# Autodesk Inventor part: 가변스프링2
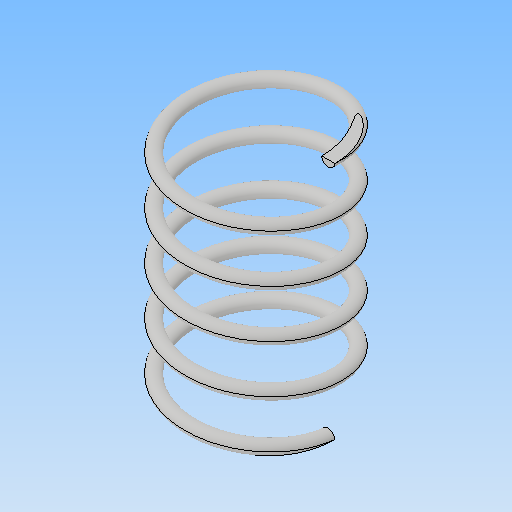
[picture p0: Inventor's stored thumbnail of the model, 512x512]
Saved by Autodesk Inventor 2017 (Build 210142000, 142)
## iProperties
Part Number: 가변스프링2
Material: 일반
Document SubType Name: Modeling
Designer: MRC
Density: 1 g/cm^3
Appearance: 기본값
Mass: 1.07362 g
Surface Area: 21.7305 cm^2
Volume: 1.07362 cm^3
Author: MRC
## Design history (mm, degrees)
sketch "스케치1"
  geometry: L1 (0, 0)-(0, 36.411); L2 (0, 0)-(11, 0); L3 (0, 36.411)-(11, 36.411); C1 r 1 at (11, 0)
  constraints: 6 end point, 2 horizontal, 1 centre point, 1 coincident, 1 vertical
  dimensions: "d0" = 36.4112 distance of L1.start L1.end (derived); "d1" = 11 distance of L1.start L2.end; "d2" = 2 diameter of C1
feature "코일1" pitch "d3" = 10; turns "d5" = 5; dims "d4" = 36.4112 (= d0), "d6" = 0, angle "d7" = 90 deg, angle "d8" = 90 deg, "d9" = 0, "d10" = 0
sketch "스케치2"
  geometry: L1 (36.411, 15)-(0, 15); L2 (0, 15)-(0, -15); L3 (0, -15)-(36.411, -15); L4 (36.411, -15)-(36.411, 15); 2 further points
  constraints: 8 end point, 2 parallel, 1 coincident, 1 horizontal, 1 midpoint, 1 perpendicular
  dimensions: "d11" = 30 distance of L3.end L1.start; "d12" = 36.4112 distance of L2.end L3.end (= d0)
extrude "돌출1" sketch "스케치2" stored distance "d13" = 30; taper "d14" = 0 deg
node "솔리드1"
